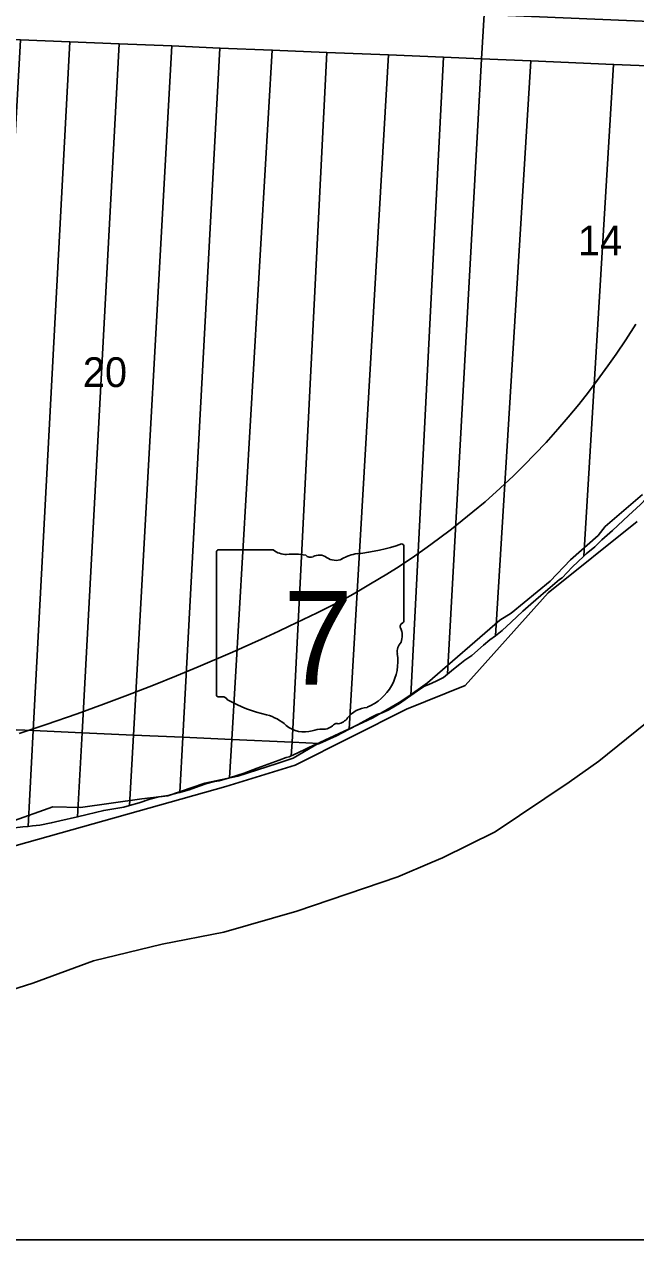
# Model space of a CAD drawing. Extents: x 396.2 to 468.4, y 232.6 to 279.1.
# Drawn here: x 423.66 to 424.52, y 264.258 to 265.969 of the extents above; entities that cross this region are included whole.
import ezdxf

# ---------------------------------------------------------------- set-up
doc = ezdxf.new("R2010")
doc.units = 0
for name, color, linetype in [('GM_X_Major_River', 7, 'Continuous'), ('GM_X_Section', 7, 'Continuous'), ('GM_X_Section_Text', 7, 'Continuous'), ('GM_X_State_Location', 7, 'Continuous'), ('GM_X_State_Route', 7, 'Continuous'), ('GM_X_State_Shield', 7, 'Continuous'), ('GM_X_Township', 7, 'Continuous'), ('SH_Cut_Line', 7, 'Continuous'), ('TX_P_1', 7, 'Continuous')]:
    doc.layers.add(name, color=color, linetype=linetype)

msp = doc.modelspace()

# ---------------------------------------------------------------- linework, layer by layer
at = {"layer": 'GM_X_Major_River'}
for points in [[(424.5302, 265.3071), (424.4775, 265.2618), (424.4677, 265.2493), (424.4287, 265.2151), (424.3999, 265.1851), (424.345, 265.1398), (424.3291, 265.1299), (424.2276, 265.0421), (424.2, 265.022), (424.1875, 265.014), (424.1504, 264.9927), (424.0761, 264.958), (424.0383, 264.936), (424.0159, 264.9283), (423.9606, 264.9104), (423.9144, 264.9005), (423.8621, 264.883), (423.8253, 264.8787), (423.7393, 264.8665), (423.7003, 264.8675), (423.64, 264.8458)], [(423.5967, 264.5953), (423.6721, 264.619), (423.7574, 264.6506), (423.854, 264.6739), (423.9411, 264.6911), (424.0434, 264.7205), (424.1855, 264.7689), (424.234, 264.7894), (424.2484, 264.7955), (424.3226, 264.8321), (424.4268, 264.9021), (424.4684, 264.9317), (424.6146, 265.0492)]]:
    msp.add_lwpolyline(points, dxfattribs=at)
at = {"layer": 'GM_X_Section'}
for points in [[(424.307, 265.9824), (424.3036, 265.92), (424.2498, 265.9223), (424.1725, 265.9255), (424.0858, 265.9291), (424.009, 265.9323), (423.9355, 265.9353), (423.8676, 265.9382), (423.7934, 265.9413), (423.724, 265.9441), (423.6546, 265.947), (423.588, 265.9498), (423.5421, 265.9517), (423.5001, 265.9535), (423.4544, 265.9554), (423.4134, 265.9571), (423.3774, 265.9586), (423.3387, 265.9602), (423.2945, 265.962), (423.2972, 266.0233)], [(424.9411, 265.9555), (424.9397, 265.9486), (424.937, 265.9395), (424.9344, 265.93), (424.9329, 265.9266), (424.9307, 265.9141), (424.9281, 265.9001), (424.927, 265.8941), (424.6452, 265.9058), (424.4894, 265.9123), (424.3728, 265.9171), (424.3036, 265.92), (424.307, 265.9824)], [(423.6546, 265.947), (423.724, 265.9441), (423.6728, 264.9746), (423.601, 264.9778)], [(423.724, 265.9441), (423.7934, 265.9413), (423.7414, 264.9715), (423.6728, 264.9746)], [(423.7934, 265.9413), (423.8676, 265.9382), (423.8137, 264.9683), (423.7414, 264.9715)], [(423.8676, 265.9382), (423.9355, 265.9353), (423.8831, 264.9652), (423.8137, 264.9683)], [(423.9355, 265.9353), (424.009, 265.9323), (423.952, 264.9621), (423.8831, 264.9652)], [(424.009, 265.9323), (424.0858, 265.9291), (424.0369, 264.9584), (423.952, 264.9621)], [(424.0858, 265.9291), (424.1725, 265.9255), (424.1174, 264.9767), (424.0996, 264.9673), (424.0754, 264.9566), (424.0369, 264.9584)], [(424.1725, 265.9255), (424.2498, 265.9223), (424.2038, 265.0239), (424.1881, 265.0127), (424.1723, 265.0032), (424.1636, 264.9998), (424.156, 264.9971), (424.1477, 264.9933), (424.1299, 264.9833), (424.1174, 264.9767)], [(424.2498, 265.9223), (424.3036, 265.92), (424.2555, 265.0541), (424.2498, 265.0493), (424.2434, 265.0459), (424.2396, 265.044), (424.2294, 265.0394), (424.2233, 265.0371), (424.218, 265.034), (424.2038, 265.0239)], [(424.3036, 265.92), (424.3728, 265.9171), (424.3232, 265.108), (424.3151, 265.1026), (424.3061, 265.095), (424.2898, 265.0802), (424.28, 265.0737), (424.2732, 265.0683), (424.2688, 265.0649), (424.2611, 265.0588), (424.2555, 265.0541)], [(424.3728, 265.9171), (424.4894, 265.9123), (424.4473, 265.22), (424.4311, 265.2049), (424.4171, 265.1897), (424.4134, 265.1871), (424.41, 265.1844), (424.4032, 265.1787), (424.3869, 265.1646), (424.3729, 265.1528), (424.3616, 265.1429), (424.3454, 265.1273), (424.3325, 265.1155), (424.3232, 265.108)], [(424.4894, 265.9123), (424.6452, 265.9058), (424.6103, 265.3814), (424.6071, 265.3776), (424.598, 265.3673), (424.5882, 265.3567), (424.5769, 265.3452), (424.5652, 265.3335), (424.5599, 265.3281), (424.5493, 265.3156), (424.5437, 265.3103), (424.5274, 265.2928), (424.5104, 265.2772), (424.4878, 265.2563), (424.473, 265.2433), (424.4628, 265.2335), (424.4508, 265.2232), (424.4473, 265.22)], [(423.6728, 264.9746), (423.6657, 264.8399), (423.6579, 264.8392), (423.6424, 264.8373), (423.6223, 264.8334), (423.6102, 264.83), (423.5981, 264.8265), (423.5926, 264.8254), (423.601, 264.9778)], [(423.7414, 264.9715), (423.7351, 264.8535), (423.7102, 264.8477), (423.6981, 264.8447), (423.6821, 264.8416), (423.6715, 264.8404), (423.6657, 264.8399), (423.6728, 264.9746)], [(423.8137, 264.9683), (423.8082, 264.8692), (423.8003, 264.867), (423.7719, 264.8624), (423.7488, 264.8566), (423.7351, 264.8535), (423.7414, 264.9715)], [(423.8831, 264.9652), (423.8789, 264.8877), (423.876, 264.887), (423.8624, 264.8835), (423.8495, 264.8816), (423.8366, 264.8781), (423.8219, 264.8731), (423.8082, 264.8692), (423.8137, 264.9683)], [(423.952, 264.9621), (423.9488, 264.908), (423.9343, 264.9039), (423.9278, 264.9031), (423.9169, 264.9004), (423.9063, 264.8966), (423.8923, 264.8912), (423.8789, 264.8877), (423.8831, 264.9652)], [(424.0369, 264.9584), (424.0356, 264.9391), (424.0327, 264.9379), (424.0285, 264.9368), (424.0187, 264.9329), (423.988, 264.9218), (423.9695, 264.9146), (423.9488, 264.908), (423.952, 264.9621)], [(424.0754, 264.9566), (424.0675, 264.954), (424.0598, 264.9503), (424.0539, 264.9475), (424.0391, 264.9406), (424.0356, 264.9391), (424.0369, 264.9584)]]:
    msp.add_lwpolyline(points, close=True, dxfattribs=at)
at = {"layer": 'GM_X_State_Route'}
msp.add_lwpolyline([(423.6529, 264.9705), (423.6909, 264.9831), (423.7343, 264.9983), (423.7717, 265.0118), (423.8054, 265.0246), (423.8419, 265.0387), (423.8742, 265.0517), (423.9046, 265.0644), (423.9531, 265.0852), (423.9939, 265.1035), (424.0182, 265.1146), (424.0328, 265.1215), (424.0525, 265.1308), (424.0721, 265.1404), (424.0864, 265.1476), (424.103, 265.1561), (424.1194, 265.1649), (424.1331, 265.1727), (424.1474, 265.181), (424.1702, 265.1948), (424.1875, 265.2057), (424.2092, 265.2202), (424.227, 265.2327), (424.2431, 265.2444), (424.2613, 265.2583), (424.2914, 265.2824), (424.3085, 265.2968), (424.3297, 265.3159), (424.3483, 265.3333), (424.3634, 265.3481), (424.3786, 265.3636), (424.3943, 265.3803), (424.4109, 265.3988), (424.4255, 265.4157), (424.4402, 265.4334), (424.454, 265.4509), (424.4664, 265.4673), (424.4814, 265.4878), (424.4931, 265.5046), (424.5066, 265.5248), (424.5205, 265.5468)], dxfattribs=at)
at = {"layer": 'GM_X_State_Shield'}
for p, q in [((424.0103, 265.229), (423.9331, 265.229)), ((424.1942, 265.1293), (424.1942, 265.2339)), ((423.9305, 265.2255), (423.9305, 265.0254)), ((424.1941, 265.1293), (424.1942, 265.1293))]:
    msp.add_line(p, q, dxfattribs=at)
for centre, radius, start, end in [((423.9335, 265.226), 0.00305, 98.1301, 188.1301), ((424.0287, 265.2522), 0.0296, 231.6195, 271.1119), ((424.1002, 265.5018), 0.2796, 275.8445, 288.9065), ((424.1912, 265.2344), 0.00294, 351.8621, 97.738), ((424.0385, 265.1166), 0.1064, 80.4867, 94.9883), ((424.0627, 265.227), 0.00855, 219.7921, 297.1024), ((424.0752, 265.2039), 0.0178, 54.4667, 119.1411), ((424.0982, 265.2356), 0.0214, 233.8562, 294.8282), ((424.1359, 265.1679), 0.0563, 97.3462, 120.7689), ((424.1935, 265.1216), 0.00454, 107.944, 210.337), ((424.191, 265.1289), 0.00314, 289.6038, 7.7341), ((424.1646, 265.1083), 0.0273, 340.033, 23.6496), ((424.2047, 265.0854), 0.0198, 136.8065, 186.9296), ((424.1159, 265.0721), 0.0699, 292.3089, 8.9858), ((423.9336, 265.025), 0.00308, 171.9584, 258.3066), ((423.934, 265.0455), 0.0235, 267.339, 280.6039), ((423.9388, 265.0139), 0.00848, 29.7484, 93.2717), ((424.0459, 265.1937), 0.2019, 240.4129, 257.1985), ((424.1454, 264.9692), 0.0383, 94.4031, 142.5768), ((423.9857, 264.9355), 0.0632, 47.1842, 75.836), ((424.0969, 265.006), 0.0226, 282.8732, 323.2771), ((424.054, 265.0129), 0.0401, 230.7004, 286.2918), ((424.0772, 264.9437), 0.0329, 85.6951, 111.2099), ((424.0801, 264.9979), 0.0214, 268.777, 315.5493), ((424.0994, 264.9785), 0.00601, 65.7517, 132.6484)]:
    msp.add_arc(centre, radius, start, end, dxfattribs=at)
at = {"layer": 'GM_X_Township'}
msp.add_lwpolyline([(424.5226, 265.269), (424.3974, 265.1684), (424.2806, 265.0379), (424.1978, 265.0046), (424.0414, 264.926), (423.9438, 264.8962), (423.6485, 264.813), (423.4509, 264.8004), (423.3832, 264.7796), (423.2178, 264.7664), (423.0657, 264.7713), (423.0026, 264.7679), (422.8972, 264.7611), (422.871, 264.7692), (422.8275, 264.7637), (422.7219, 264.7888), (422.6322, 264.7777), (422.4717, 264.7433), (422.3706, 264.7592)], dxfattribs=at)
at = {"layer": 'SH_Cut_Line'}
msp.add_lwpolyline([(422.3706, 264.7592), (422.4717, 264.7433), (422.6322, 264.7777), (422.7219, 264.7888), (422.8275, 264.7637), (422.871, 264.7692), (422.8972, 264.7611), (423.0026, 264.7679), (423.0657, 264.7713), (423.2178, 264.7664), (423.3832, 264.7796), (423.4509, 264.8004), (423.6485, 264.813), (423.9438, 264.8962), (424.0414, 264.926), (424.1978, 265.0046), (424.2806, 265.0379), (424.3974, 265.1684), (424.5226, 265.269)], dxfattribs=at)
at = {"layer": 'TX_P_1'}
msp.add_line((427.4513, 264.2582), (413.8513, 264.2582), dxfattribs=at)

# ---------------------------------------------------------------- texts
at = {"layer": 'GM_X_Section_Text'}
for s, p in [('14', (424.4392, 265.6435)), ('20', (423.7425, 265.4582))]:
    msp.add_text(s, height=0.04186, rotation=0, dxfattribs=at).set_placement(p)
at = {"layer": 'GM_X_State_Location'}
for s in ['s', 'r']:
    msp.add_text(s, height=0.000189, dxfattribs=at).set_placement((424.0594, 265.1122))
msp.add_text('7', height=0.000189, rotation=0, dxfattribs=at).set_placement((424.0308, 265.0984))
at = {"layer": 'GM_X_State_Shield'}
msp.add_text('7', height=0.1318, dxfattribs=at).set_placement((424.0246, 265.0395))

doc.saveas('drawing.dxf')
